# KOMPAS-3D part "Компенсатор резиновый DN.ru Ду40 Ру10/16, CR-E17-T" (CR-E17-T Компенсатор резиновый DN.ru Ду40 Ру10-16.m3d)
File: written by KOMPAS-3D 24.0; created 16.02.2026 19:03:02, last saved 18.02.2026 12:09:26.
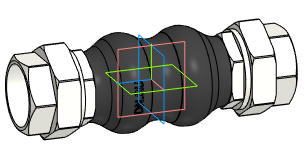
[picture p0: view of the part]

Document properties: Автор: DN.RU; Полное имя файла: CR-E17-T Компенсатор резиновый DN.ru Ду40 Ру10-16.cdw

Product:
- Body: Твердое тело1  | qty 1
    Масса: 2.35583
- Part/product: Компенсатор резиновый DN.ru Ду40 Ру10/16  | designation CR-E17-T
    Масса: 2.08
    Раздел спецификации: Прочие изделия
    Форматы листов документа: A3
    Комментарий: D140-02213
    Примечание: D140-02213
    additional columns: Типовые

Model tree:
1. Твердое тело1  (labels: Твердое тело1)

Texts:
  CR-E17-T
